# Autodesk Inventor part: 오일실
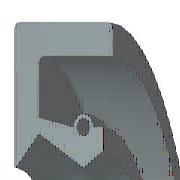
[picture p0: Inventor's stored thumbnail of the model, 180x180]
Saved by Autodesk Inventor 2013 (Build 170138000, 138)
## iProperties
Created: 2015-11
Part Number: 오일실
Material: 고무
Description: 오일-실
Document SubType Name: Modeling
Standard: KS B 2804
Designer: mdu
Standards Organization: KS
Language: ko-KR
Size Designation: D - 10 20 7
Categories: <MemberInstance><Categories><Category DisplayName="샤프트 부품" InternalName="7f7aeb1f-a693-4053-b835-cee3144e0d98" Mnemonic="SHFT"><Category DisplayName="실링" Intern
Density: 0.93 g/cm^3
IsCustomPart: 0
Author: mdu
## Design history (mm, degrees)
revolve "본체" stored, may be unused: angle "d17" = 90 deg
revolve "스프링1" stored, may be unused: angle "d18" = 90 deg
body "Solid1"
sketch "스케치1"
  geometry: L1 (0, 10)-(7, 10); L2 (7, 8.25)-(1.75, 8.25); L3 (1.75, 6.75)-(4.9, 5); L4 (4.9, 5)-(0, 5); L5 (0, 0)-(9.586, 0) reference; L6 (4.9, 5)-(6.3, 5.875); L7 (0, 18)-(0, -3) reference; L8 (-1.941, 0)-(11.507, 0) reference; L9 (4.2, 7.1)-(1.75, 7.59); L10 (1.75, 7.59)-(1.75, 8.25); L11 (0, 10)-(0, 5.088); L12 (4.9, 5)-(0, 5); L13 (1.75, 6.75)-(0.152, 5.028); L14 (7, 10)-(7, 8.25); L15 (5.6, 7.1)-(6.3, 7.1); L16 (6.3, 7.1)-(6.3, 5.875); C1 r 0.455 at (4.9, 7.1); A1 r 0.7 centre (4.9, 7.1) between (5.6, 7.1) and (4.2, 7.1); A2 r 0.088 centre (0.088, 5.088) between (0, 5.088) and (0.152, 5.028); 1 further point
  constraints: 28 end point, 5 horizontal alignment, 5 point on line, 4 point on circle, 4 vertical alignment, 3 centre point, 3 tangent, 2 collinear, 2 horizontal, 2 perpendicular, 1 coincident, 1 parallel
  dimensions: "d0" = 20 diameter of L1 L5 (= SD2); "d1" = 1.75 distance of L1.end L2.start (= SD); "d2" = 0.91 diameter of C1 (= SPDI); "d3" = 1.4 diameter of A1 (= SPDA); "d4" = 10 diameter of L3.end L5 (= NND); "d5" = 13.5 diameter of L3.start L5 (= TKDM); "d7" = 15.18 diameter of L9.end L5 (= TKDM + 0.24 x SWDT); "d8" = 1.75 distance between parallel lines of L11 L10 (= SD); "d9" = 4.9 distance from line of L11 C1.centre (= SPDST); "d10" = 14.2 diameter of C1.centre L5 (= HLDM); "d11" = 0.0875 radius of A2 (= 0.25 x LAB); "d12" = 6.3 distance between parallel lines of L11 L16 (= SDI); "d13" = 11.75 diameter of L6.end L5 (= ABDM); "d14" = 7 distance from line of L11 L1.end (= SWDT)
fillet "모깎기1" dims "d6" = 0.3 (= RR)
other parameters: "SD2" = 20 [user parameter; used in 1 equation term], "SWDT" = 7 [user parameter; used in 2 equation terms], "RR" = 0.3 [user parameter; used in 1 equation term], "SD" = 1.75 [user parameter; used in 2 equation terms], "NND" = 10 [user parameter; used in 1 equation term], "SPDA" = 1.4 [user parameter; used in 1 equation term], "SPDI" = 0.91 [user parameter; used in 1 equation term], "TKDM" = 13.5 [user parameter; used in 2 equation terms], "HLDM" = 14.2 [user parameter; used in 1 equation term], "ABDM" = 11.75 [user parameter; used in 1 equation term], "SDI" = 6.3 [user parameter; used in 1 equation term], "SPDST" = 4.9 [user parameter; used in 1 equation term], "LAB" = 0.35 [user parameter; used in 1 equation term], "d15" = 0, "d16" = 0, "d19" = 0
